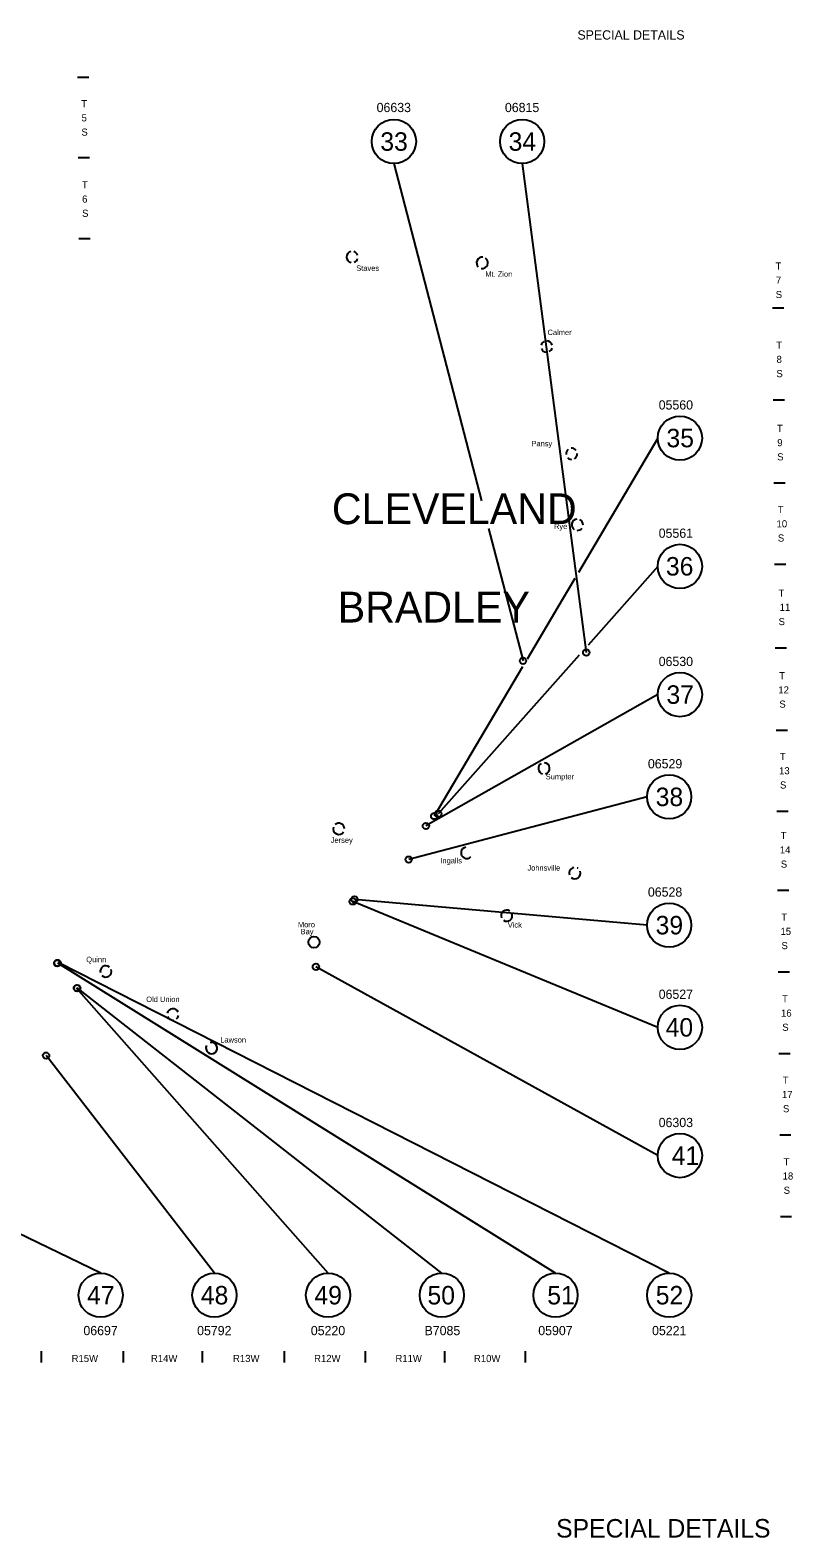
# Model space of a CAD drawing. Extents: x 3046 to 131673, y -8885 to 10756.
# Drawn here: x 121774 to 131673, y -8826 to 10746 of the extents above; entities that cross this region are included whole.
import ezdxf

# ---------------------------------------------------------------- set-up
doc = ezdxf.new("R2010")
doc.units = 0
for name, color, linetype in [('2', 7, 'Continuous'), ('Default', 7, 'Continuous'), ('Level 24', 7, 'Continuous'), ('R_Annotation', 7, 'Continuous'), ('R_Border', 7, 'Continuous'), ('R_No Plot', 7, 'Continuous')]:
    doc.layers.add(name, color=color, linetype=linetype)

msp = doc.modelspace()

# ---------------------------------------------------------------- linework, layer by layer
at = {"layer": 'Default'}
for p, q in [((122534, 10132), (122387, 10132)), ((122543, 9089), (122397, 9089)), ((122552, 8036), (122406, 8036)), ((131555, 7135), (131409, 7135)), ((131555, 7135), (131409, 7135)), ((131555, 7135), (131409, 7135)), ((131564, 5944), (131418, 5944)), ((131564, 5944), (131418, 5944)), ((131564, 5944), (131418, 5944)), ((131574, 4863), (131427, 4863)), ((131574, 4863), (131427, 4863)), ((131574, 4863), (131427, 4863)), ((131583, 3809), (131437, 3809)), ((131583, 3809), (131437, 3809)), ((131583, 3809), (131437, 3809)), ((131592, 2724), (131446, 2724)), ((131592, 2724), (131446, 2724)), ((131592, 2724), (131446, 2724)), ((131602, 1653), (131456, 1653)), ((131602, 1653), (131456, 1653)), ((131602, 1653), (131456, 1653)), ((131611, 603), (131465, 603)), ((131621, -424), (131474, -424)), ((131630, -1482), (131484, -1482)), ((131640, -2542), (131493, -2542)), ((131649, -3599), (131503, -3599)), ((131658, -4658), (131512, -4658)), ((121918, -6403), (121918, -6550)), ((122983, -6403), (122983, -6550)), ((124006, -6403), (124006, -6550)), ((125070, -6403), (125070, -6550)), ((126122, -6403), (126122, -6550)), ((127152, -6403), (127152, -6550)), ((128201, -6403), (128201, -6550))]:
    msp.add_line(p, q, dxfattribs=at)
at = {"layer": 'Level 24'}
msp.add_circle((125458, -1093), 73.3, dxfattribs=at)
for centre, start, end in [((125954, 7801), 103.0693, 258.8708), ((125954, 7801), 15.6795, 71.5651), ((125954, 7801), 291.2505, 343.664), ((127642, 7726), 83.6598, 225), ((127642, 7726), 259.8245, 53.0357), ((128478, 6638), 118.1971, 165.0989), ((128478, 6638), 16.288, 87.3237), ((128478, 6638), 199.2501, 266.857), ((128478, 6638), 298.0009, 344.9135), ((128802, 5246), 129.7663, 188.3285), ((128802, 5246), 36.1881, 95.8348), ((128802, 5246), 224.5732, 267.0622), ((128802, 5246), 300.3026, 3.607), ((128877, 4325), 97.4808, 236.0917), ((128877, 4325), 356.3631, 65.9346), ((128877, 4325), 268.2955, 324.7673), ((128443, 1163), 119.2217, 254.2487), ((128443, 1163), 286.6637, 86.2671), ((125780, 378), 163.6329, 326.774), ((125780, 378), 0.2243, 131.161), ((127439, 67), 98.9199, 317.161), ((128844, -198), 99.9506, 196.0817), ((128844, -198), 231.0275, 20.0261), ((128844, -198), 53.6372, 66.8014), ((127959, -749), 55.1213, 202.0527), ((127959, -749), 234.7334, 22.1102), ((122757, -1473), 51.3736, 191.3937), ((122757, -1473), 225, 18.3011), ((123626, -2031), 23.3691, 168.5213), ((123626, -2031), 202.8645, 274.0401), ((123626, -2031), 308.5583, 348.5213), ((124128, -2468), 153.8182, 104.3493)]:
    msp.add_arc(centre, 73.3, start, end, dxfattribs=at)
at = {"layer": 'R_Annotation'}
for p, q in [((126495, 9013), (127632, 4634)), ((128160, 9013), (128992, 2666)), ((129922, 5450), (128890, 3706)), ((127725, 4276), (128171, 2559)), ((129922, 3785), (129016, 2764)), ((128844, 3628), (128680, 3350)), ((128680, 3350), (128225, 2581)), ((128899, 2632), (127070, 572)), ((128166, 2482), (127019, 543)), ((129922, 2120), (126911, 415)), ((129782, 793), (126687, -21)), ((129922, -2199), (125961, -564)), ((129782, -872), (125984, -538)), ((128593, -5389), (122131, -1367)), ((130069, -5389), (122136, -1359)), ((129922, -3864), (125483, -1413)), ((125641, -5389), (122377, -1691)), ((127117, -5389), (122385, -1684)), ((124165, -5389), (121980, -2566)), ((122689, -5389), (120076, -4125))]:
    msp.add_line(p, q, dxfattribs=at)
for centre, radius in [((126495, 9300), 287), ((128160, 9300), 287), ((130208, 5450), 287), ((130208, 3785), 287), ((128171, 2559), 41.7), ((128992, 2666), 41.7), ((130208, 2120), 287), ((130068, 793), 287), ((127070, 572), 41.7), ((126911, 415), 41.7), ((127019, 543), 41.7), ((126687, -21), 41.7), ((125961, -564), 41.7), ((125984, -538), 41.7), ((130068, -872), 287), ((122125, -1368), 41.7), ((122129, -1363), 41.7), ((125483, -1413), 41.7), ((122381, -1688), 41.7), ((122385, -1690), 41.7), ((130208, -2199), 287), ((121980, -2566), 41.7), ((130208, -3864), 287), ((122689, -5676), 287), ((124165, -5676), 287), ((125641, -5676), 287), ((127117, -5676), 287), ((128593, -5676), 287), ((130069, -5676), 287)]:
    msp.add_circle(centre, radius, dxfattribs=at)

# ---------------------------------------------------------------- texts
at = {"layer": '2'}
for s, height, p in [('T', 92.4, (122437, 9746)), ('5', 92.4, (122441, 9561)), ('S', 92.4, (122439, 9376)), ('T', 92.4, (122447, 8692)), ('6', 92.4, (122448, 8507)), ('S', 92.4, (122448, 8322)), ('T', 92.4, (131449, 7638)), ('7', 92.4, (131453, 7453)), ('S', 92.4, (131451, 7268)), ('T', 92.4, (131458, 6611)), ('8', 92.4, (131462, 6426)), ('S', 92.4, (131460, 6241)), ('T', 92.4, (131468, 5530)), ('9', 92.4, (131471, 5345)), ('S', 92.4, (131470, 5161)), ('CLEVELAND', 399.6, (125690, 4333)), ('T', 92.4, (131477, 4476)), ('10', 92.4, (131462, 4292)), ('S', 92.4, (131479, 4107)), ('BRADLEY', 399.6, (125766, 3056)), ('T', 92.4, (131487, 3392)), ('11', 92.4, (131502, 3207)), ('S', 92.4, (131488, 3022)), ('T', 92.4, (131496, 2320)), ('12', 92.4, (131485, 2135)), ('S', 92.4, (131498, 1951)), ('13', 92.4, (131494, 1086)), ('T', 92.4, (131505, 1271)), ('S', 92.4, (131507, 901)), ('T', 92.4, (131515, 244)), ('14', 92.4, (131504, 59)), ('S', 92.4, (131517, -126)), ('T', 92.4, (131524, -814)), ('15', 92.4, (131513, -999)), ('S', 92.4, (131526, -1184)), ('T', 92.4, (131534, -1875)), ('16', 92.4, (131520, -2060)), ('S', 92.4, (131536, -2244)), ('T', 92.4, (131543, -2932)), ('17', 92.4, (131532, -3116)), ('S', 92.4, (131545, -3301)), ('T', 92.4, (131553, -3991)), ('18', 92.4, (131541, -4175)), ('S', 92.4, (131554, -4360)), ('R15W', 92.4, (122312, -6543)), ('R14W', 92.4, (123342, -6543)), ('R13W', 92.4, (124407, -6543)), ('R12W', 92.4, (125459, -6543)), ('R11W', 92.4, (126515, -6543)), ('R10W', 92.4, (127534, -6543))]:
    msp.add_text(s, height=height, dxfattribs=at).set_placement(p)
at = {"layer": 'Level 24'}
for s, p in [('Staves', (126006, 7621)), ('Mt. Zion', (127681, 7544)), ('Calmer', (128489, 6788)), ('Pansy', (128280, 5344)), ('Rye', (128573, 4270)), ('Sumpter', (128466, 1020)), ('Jersey', (125675, 196)), ('Ingalls', (127098, -70)), ('Johnsville', (128228, -164)), ('Moro', (125249, -900)), ('Bay', (125284, -991)), ('Vick', (127973, -904)), ('Quinn', (122502, -1353)), ('Old Union', (123280, -1870)), ('Lawson', (124241, -2396))]:
    msp.add_text(s, height=70.4, dxfattribs=at).set_placement(p)
at = {"layer": 'R_Annotation'}
for s, height, p in [('33', 239.8, (126319, 9180)), ('34', 239.8, (127984, 9180)), ('35', 239.8, (130033, 5331)), ('36', 239.8, (130026, 3666)), ('37', 239.8, (130033, 2001)), ('38', 239.8, (129893, 673)), ('39', 239.8, (129892, -992)), ('40', 239.8, (130022, -2319)), ('41', 239.8, (130101, -3984)), ('47', 239.8, (122513, -5796)), ('48', 239.8, (123989, -5796)), ('49', 239.8, (125464, -5796)), ('50', 239.8, (126931, -5796)), ('51', 239.8, (128486, -5796)), ('52', 239.8, (129894, -5796)), ('SPECIAL DETAILS', 240, (128601, -8822))]:
    msp.add_text(s, height=height, dxfattribs=at).set_placement(p)
at = {"layer": 'R_Border'}
msp.add_text('SPECIAL DETAILS', height=120, dxfattribs=at).set_placement((128877, 10624))
at = {"layer": 'R_No Plot'}
for s, p in [('06633', (126271, 9682)), ('06633', (126271, 9682)), ('06815', (127936, 9682)), ('05560', (129932, 5821)), ('05561', (129932, 4156)), ('06530', (129932, 2491)), ('06529', (129792, 1163)), ('06528', (129792, -502)), ('06527', (129932, -1829)), ('06303', (129932, -3494)), ('06697', (122465, -6195)), ('05792', (123941, -6195)), ('05220', (125417, -6195)), ('B7085', (126893, -6195)), ('05907', (128369, -6195)), ('05221', (129846, -6195))]:
    msp.add_text(s, height=119.9, dxfattribs=at).set_placement(p)

doc.saveas('drawing.dxf')
